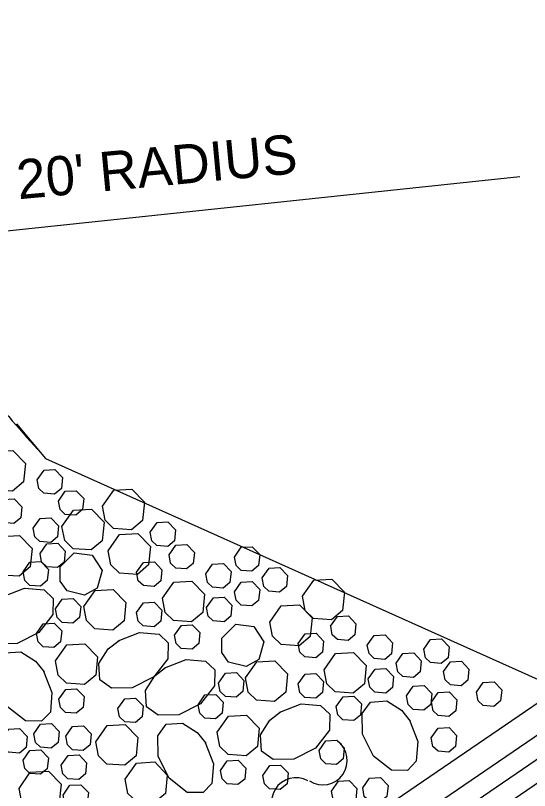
# Model space of a CAD drawing. Extents: x 6709491 to 6710959, y 1869789 to 1870763.
# Drawn here: x 6709842.4 to 6709921, y 1870319.2 to 1870437.5 of the extents above; entities that cross this region are included whole.
import ezdxf

# ---------------------------------------------------------------- set-up
doc = ezdxf.new("R2010")
doc.units = 0
for name, color, linetype in [('56 Stg 3 Anno', 7, 'Continuous'), ('57 Undefined', 7, 'Continuous'), ('60 Nongeo Data', 7, 'Continuous')]:
    doc.layers.add(name, color=color, linetype=linetype)

msp = doc.modelspace()

# ---------------------------------------------------------------- linework, layer by layer
at = {"layer": '56 Stg 3 Anno'}
msp.add_line((6709828.3, 1870403.28), (6709919.48, 1870412.91), dxfattribs=at)
at = {"layer": '60 Nongeo Data'}
for p, q in [((6709846.99, 1870369.89), (6709929.61, 1870332.83)), ((6709845.05, 1870279.98), (6709922.46, 1870332.74)), ((6709851.95, 1870279.8), (6709924.47, 1870329.23)), ((6709855.14, 1870278.31), (6709927.7, 1870327.77)), ((6709858.32, 1870276.81), (6709928.82, 1870324.87))]:
    msp.add_line(p, q, dxfattribs=at)
for points in [[(6709842.58, 1870375.18), (6709846.99, 1870369.89)], [(6709837.48, 1870368.48), (6709839.22, 1870370.95), (6709841.99, 1870371.11), (6709843.92, 1870369.11), (6709843.65, 1870366.3), (6709841.93, 1870364.88), (6709839.19, 1870365.08), (6709837.9, 1870366.33), (6709837.48, 1870368.48)], [(6709845.72, 1870366.6), (6709846.76, 1870368.09), (6709848.43, 1870368.18), (6709849.59, 1870366.98), (6709849.42, 1870365.3), (6709848.39, 1870364.44), (6709846.74, 1870364.56), (6709845.97, 1870365.31), (6709845.72, 1870366.6)], [(6709848.97, 1870363.37), (6709850.02, 1870364.86), (6709851.68, 1870364.95), (6709852.84, 1870363.75), (6709852.67, 1870362.07), (6709851.64, 1870361.21), (6709850, 1870361.33), (6709849.22, 1870362.08), (6709848.97, 1870363.37)], [(6709855.68, 1870362.58), (6709857.41, 1870365.05), (6709860.19, 1870365.21), (6709862.12, 1870363.21), (6709861.84, 1870360.4), (6709860.13, 1870358.98), (6709857.38, 1870359.18), (6709856.09, 1870360.43), (6709855.68, 1870362.58)], [(6709839.49, 1870362.12), (6709840.54, 1870363.61), (6709842.2, 1870363.7), (6709843.36, 1870362.5), (6709843.2, 1870360.82), (6709842.17, 1870359.96), (6709840.52, 1870360.08), (6709839.75, 1870360.83), (6709839.5, 1870362.12)], [(6709849.51, 1870359.5), (6709851.25, 1870361.97), (6709854.02, 1870362.13), (6709855.95, 1870360.13), (6709855.67, 1870357.32), (6709853.96, 1870355.9), (6709851.22, 1870356.1), (6709849.93, 1870357.35), (6709849.51, 1870359.5)], [(6709845.1, 1870359.22), (6709846.15, 1870360.7), (6709847.81, 1870360.8), (6709848.97, 1870359.6), (6709848.8, 1870357.92), (6709847.78, 1870357.06), (6709846.13, 1870357.18), (6709845.36, 1870357.93), (6709845.11, 1870359.22)], [(6709863, 1870358.61), (6709864.04, 1870360.09), (6709865.71, 1870360.19), (6709866.86, 1870358.99), (6709866.7, 1870357.3), (6709865.67, 1870356.45), (6709864.02, 1870356.57), (6709863.25, 1870357.32), (6709863, 1870358.61)], [(6709867.9, 1870359.51), (6709867.9, 1870359.51)], [(6709838.49, 1870355.48), (6709840.22, 1870357.96), (6709843, 1870358.11), (6709844.93, 1870356.11), (6709844.65, 1870353.31), (6709842.94, 1870351.88), (6709840.2, 1870352.08), (6709838.9, 1870353.33), (6709838.49, 1870355.48)], [(6709856.58, 1870355.78), (6709858.32, 1870358.26), (6709861.1, 1870358.42), (6709863.03, 1870356.41), (6709862.75, 1870353.61), (6709861.03, 1870352.18), (6709858.29, 1870352.38), (6709857, 1870353.63), (6709856.58, 1870355.78)], [(6709846.15, 1870355.37), (6709847.19, 1870356.85), (6709848.86, 1870356.95), (6709850.02, 1870355.74), (6709849.85, 1870354.06), (6709848.82, 1870353.21), (6709847.17, 1870353.33), (6709846.4, 1870354.08), (6709846.15, 1870355.36)], [(6709865.87, 1870355.16), (6709866.91, 1870356.64), (6709868.58, 1870356.74), (6709869.74, 1870355.54), (6709869.57, 1870353.85), (6709868.54, 1870353), (6709866.9, 1870353.12), (6709866.12, 1870353.87), (6709865.87, 1870355.16)], [(6709875.86, 1870354.82), (6709876.91, 1870356.31), (6709878.57, 1870356.4), (6709879.73, 1870355.2), (6709879.56, 1870353.52), (6709878.53, 1870352.66), (6709876.89, 1870352.78), (6709876.11, 1870353.53), (6709875.86, 1870354.82)], [(6709849.21, 1870353.33), (6709851.37, 1870355.45), (6709854.13, 1870355.1), (6709855.67, 1870352.78), (6709854.88, 1870350.07), (6709852.94, 1870348.98), (6709850.28, 1870349.67), (6709849.23, 1870351.14), (6709849.21, 1870353.33)], [(6709843.56, 1870352.54), (6709844.6, 1870354.02), (6709846.27, 1870354.12), (6709847.43, 1870352.92), (6709847.26, 1870351.24), (6709846.23, 1870350.38), (6709844.58, 1870350.5), (6709843.81, 1870351.25), (6709843.56, 1870352.54)], [(6709860.92, 1870352.5), (6709861.97, 1870353.99), (6709863.63, 1870354.08), (6709864.79, 1870352.88), (6709864.62, 1870351.2), (6709863.59, 1870350.34), (6709861.95, 1870350.46), (6709861.17, 1870351.21), (6709860.92, 1870352.5)], [(6709871.48, 1870352.25), (6709872.52, 1870353.74), (6709874.19, 1870353.83), (6709875.35, 1870352.63), (6709875.18, 1870350.95), (6709874.15, 1870350.09), (6709872.51, 1870350.21), (6709871.73, 1870350.96), (6709871.48, 1870352.25)], [(6709880.11, 1870351.63), (6709881.16, 1870353.12), (6709882.82, 1870353.21), (6709883.98, 1870352.01), (6709883.81, 1870350.33), (6709882.78, 1870349.47), (6709881.14, 1870349.59), (6709880.36, 1870350.34), (6709880.11, 1870351.63)], [(6709864.86, 1870348.52), (6709866.6, 1870350.99), (6709869.38, 1870351.15), (6709871.31, 1870349.15), (6709871.03, 1870346.34), (6709869.31, 1870344.92), (6709866.57, 1870345.11), (6709865.28, 1870346.36), (6709864.86, 1870348.52)], [(6709875.86, 1870349.51), (6709876.91, 1870350.99), (6709878.57, 1870351.09), (6709879.73, 1870349.88), (6709879.56, 1870348.2), (6709878.53, 1870347.35), (6709876.89, 1870347.47), (6709876.11, 1870348.22), (6709875.86, 1870349.51)], [(6709886.25, 1870348.84), (6709887.99, 1870351.31), (6709890.76, 1870351.47), (6709892.69, 1870349.47), (6709892.41, 1870346.66), (6709890.7, 1870345.24), (6709887.96, 1870345.43), (6709886.67, 1870346.68), (6709886.25, 1870348.83)], [(6709840.52, 1870348.79), (6709843.77, 1870350.08), (6709846.76, 1870349.82), (6709848.18, 1870348.47), (6709848.13, 1870346.05), (6709845.98, 1870343.29), (6709842.65, 1870341.63), (6709839.51, 1870341.57), (6709837.74, 1870342.83), (6709837.57, 1870345.33), (6709839.01, 1870347.57), (6709840.65, 1870348.88)], [(6709852.83, 1870347.26), (6709854.57, 1870349.73), (6709857.35, 1870349.89), (6709859.28, 1870347.89), (6709859, 1870345.08), (6709857.29, 1870343.66), (6709854.54, 1870343.86), (6709853.25, 1870345.11), (6709852.84, 1870347.26)], [(6709848.5, 1870346.89), (6709849.55, 1870348.37), (6709851.21, 1870348.47), (6709852.37, 1870347.27), (6709852.2, 1870345.59), (6709851.17, 1870344.73), (6709849.53, 1870344.85), (6709848.75, 1870345.6), (6709848.5, 1870346.89)], [(6709871.61, 1870347.11), (6709872.66, 1870348.6), (6709874.32, 1870348.69), (6709875.48, 1870347.49), (6709875.31, 1870345.81), (6709874.28, 1870344.95), (6709872.64, 1870345.07), (6709871.86, 1870345.82), (6709871.61, 1870347.11)], [(6709892.6, 1870348.62), (6709892.6, 1870348.62)], [(6709860.91, 1870346.34), (6709861.96, 1870347.82), (6709863.62, 1870347.92), (6709864.78, 1870346.71), (6709864.61, 1870345.03), (6709863.58, 1870344.18), (6709861.94, 1870344.3), (6709861.16, 1870345.05), (6709860.91, 1870346.34)], [(6709881.29, 1870344.89), (6709883.02, 1870347.36), (6709885.8, 1870347.52), (6709887.73, 1870345.52), (6709887.45, 1870342.71), (6709885.74, 1870341.29), (6709882.99, 1870341.49), (6709881.7, 1870342.74), (6709881.29, 1870344.89)], [(6709890.57, 1870344.26), (6709891.62, 1870345.75), (6709893.28, 1870345.84), (6709894.44, 1870344.64), (6709894.28, 1870342.96), (6709893.25, 1870342.1), (6709891.6, 1870342.22), (6709890.83, 1870342.97), (6709890.58, 1870344.26)], [(6709845.6, 1870343.17), (6709846.64, 1870344.65), (6709848.31, 1870344.75), (6709849.47, 1870343.55), (6709849.3, 1870341.86), (6709848.27, 1870341.01), (6709846.63, 1870341.13), (6709845.85, 1870341.88), (6709845.6, 1870343.17)], [(6709866.72, 1870342.9), (6709867.76, 1870344.39), (6709869.43, 1870344.48), (6709870.59, 1870343.28), (6709870.42, 1870341.6), (6709869.39, 1870340.74), (6709867.75, 1870340.86), (6709866.97, 1870341.61), (6709866.72, 1870342.9)], [(6709873.92, 1870342.43), (6709876.07, 1870344.55), (6709878.83, 1870344.2), (6709880.37, 1870341.88), (6709879.59, 1870339.18), (6709877.64, 1870338.09), (6709874.98, 1870338.78), (6709873.94, 1870340.24), (6709873.92, 1870342.43)], [(6709858.09, 1870342.02), (6709861.35, 1870343.31), (6709864.34, 1870343.05), (6709865.76, 1870341.7), (6709865.71, 1870339.28), (6709863.55, 1870336.52), (6709860.22, 1870334.85), (6709857.08, 1870334.8), (6709855.31, 1870336.05), (6709855.15, 1870338.56), (6709856.58, 1870340.79), (6709858.23, 1870342.1)], [(6709885.63, 1870341.61), (6709886.67, 1870343.09), (6709888.34, 1870343.19), (6709889.49, 1870341.99), (6709889.33, 1870340.3), (6709888.3, 1870339.45), (6709886.65, 1870339.57), (6709885.88, 1870340.32), (6709885.63, 1870341.61)], [(6709896.18, 1870341.36), (6709897.23, 1870342.84), (6709898.89, 1870342.94), (6709900.05, 1870341.74), (6709899.88, 1870340.05), (6709898.85, 1870339.2), (6709897.21, 1870339.32), (6709896.44, 1870340.07), (6709896.18, 1870341.36)], [(6709904.82, 1870340.74), (6709905.86, 1870342.22), (6709907.53, 1870342.32), (6709908.68, 1870341.11), (6709908.52, 1870339.43), (6709907.49, 1870338.58), (6709905.84, 1870338.7), (6709905.07, 1870339.45), (6709904.82, 1870340.74)], [(6709848.5, 1870338.95), (6709850.24, 1870341.43), (6709853.02, 1870341.58), (6709854.95, 1870339.58), (6709854.67, 1870336.78), (6709852.96, 1870335.35), (6709850.21, 1870335.55), (6709848.93, 1870336.8), (6709848.51, 1870338.95)], [(6709846.69, 1870337.41), (6709847.98, 1870334.15), (6709847.73, 1870331.16), (6709846.37, 1870329.74), (6709843.95, 1870329.79), (6709841.19, 1870331.94), (6709839.53, 1870335.28), (6709839.47, 1870338.42), (6709840.73, 1870340.19), (6709843.23, 1870340.35), (6709845.47, 1870338.92), (6709846.78, 1870337.28)], [(6709889.57, 1870337.62), (6709891.3, 1870340.09), (6709894.08, 1870340.25), (6709896.01, 1870338.25), (6709895.73, 1870335.45), (6709894.02, 1870334.02), (6709891.28, 1870334.22), (6709889.98, 1870335.47), (6709889.57, 1870337.62)], [(6709900.57, 1870338.61), (6709901.61, 1870340.1), (6709903.28, 1870340.19), (6709904.43, 1870338.99), (6709904.27, 1870337.31), (6709903.24, 1870336.45), (6709901.59, 1870336.57), (6709900.82, 1870337.32), (6709900.57, 1870338.61)], [(6709865.22, 1870337.9), (6709868.47, 1870339.19), (6709871.46, 1870338.93), (6709872.88, 1870337.58), (6709872.84, 1870335.15), (6709870.68, 1870332.4), (6709867.35, 1870330.73), (6709864.21, 1870330.68), (6709862.44, 1870331.93), (6709862.28, 1870334.43), (6709863.71, 1870336.67), (6709865.35, 1870337.98)], [(6709877.54, 1870336.36), (6709879.28, 1870338.84), (6709882.05, 1870339), (6709883.98, 1870336.99), (6709883.71, 1870334.19), (6709881.99, 1870332.76), (6709879.25, 1870332.96), (6709877.96, 1870334.21), (6709877.54, 1870336.36)], [(6709907.84, 1870337.34), (6709908.89, 1870338.83), (6709910.55, 1870338.92), (6709911.71, 1870337.72), (6709911.54, 1870336.04), (6709910.51, 1870335.18), (6709908.87, 1870335.3), (6709908.09, 1870336.05), (6709907.84, 1870337.34)], [(6709896.32, 1870336.22), (6709897.36, 1870337.7), (6709899.03, 1870337.8), (6709900.18, 1870336.6), (6709900.02, 1870334.92), (6709898.99, 1870334.06), (6709897.34, 1870334.18), (6709896.57, 1870334.93), (6709896.32, 1870336.22)], [(6709873.45, 1870335.59), (6709874.49, 1870337.07), (6709876.16, 1870337.17), (6709877.32, 1870335.97), (6709877.15, 1870334.28), (6709876.12, 1870333.43), (6709874.48, 1870333.55), (6709873.7, 1870334.3), (6709873.45, 1870335.59)], [(6709885.62, 1870335.44), (6709886.66, 1870336.92), (6709888.33, 1870337.02), (6709889.49, 1870335.82), (6709889.32, 1870334.14), (6709888.29, 1870333.28), (6709886.64, 1870333.4), (6709885.87, 1870334.15), (6709885.62, 1870335.44)], [(6709902.17, 1870333.61), (6709903.21, 1870335.09), (6709904.88, 1870335.19), (6709906.03, 1870333.99), (6709905.87, 1870332.31), (6709904.84, 1870331.45), (6709903.19, 1870331.57), (6709902.42, 1870332.32), (6709902.17, 1870333.61)], [(6709912.85, 1870334.18), (6709913.9, 1870335.66), (6709915.56, 1870335.76), (6709916.72, 1870334.55), (6709916.56, 1870332.87), (6709915.53, 1870332.02), (6709913.88, 1870332.14), (6709913.11, 1870332.89), (6709912.86, 1870334.18)], [(6709849.03, 1870333.13), (6709850.08, 1870334.61), (6709851.74, 1870334.71), (6709852.9, 1870333.51), (6709852.73, 1870331.83), (6709851.7, 1870330.97), (6709850.06, 1870331.09), (6709849.28, 1870331.84), (6709849.03, 1870333.13)], [(6709870.3, 1870332.27), (6709871.35, 1870333.76), (6709873.01, 1870333.85), (6709874.17, 1870332.65), (6709874, 1870330.97), (6709872.98, 1870330.11), (6709871.33, 1870330.23), (6709870.56, 1870330.98), (6709870.3, 1870332.27)], [(6709905.99, 1870332.66), (6709907.03, 1870334.14), (6709908.7, 1870334.24), (6709909.86, 1870333.03), (6709909.69, 1870331.35), (6709908.66, 1870330.5), (6709907.01, 1870330.61), (6709906.24, 1870331.36), (6709905.99, 1870332.65)], [(6709858.06, 1870331.7), (6709859.11, 1870333.19), (6709860.77, 1870333.28), (6709861.93, 1870332.08), (6709861.76, 1870330.4), (6709860.74, 1870329.54), (6709859.09, 1870329.66), (6709858.32, 1870330.41), (6709858.07, 1870331.7)], [(6709891.42, 1870332.01), (6709892.47, 1870333.49), (6709894.13, 1870333.59), (6709895.29, 1870332.39), (6709895.13, 1870330.7), (6709894.1, 1870329.85), (6709892.45, 1870329.97), (6709891.68, 1870330.72), (6709891.43, 1870332.01)], [(6709902.63, 1870329.91), (6709903.92, 1870326.65), (6709903.66, 1870323.66), (6709902.31, 1870322.24), (6709899.88, 1870322.29), (6709897.13, 1870324.44), (6709895.46, 1870327.78), (6709895.4, 1870330.92), (6709896.66, 1870332.68), (6709899.16, 1870332.85), (6709901.4, 1870331.42), (6709902.71, 1870329.78)], [(6709882.8, 1870331.13), (6709886.05, 1870332.42), (6709889.04, 1870332.16), (6709890.46, 1870330.81), (6709890.41, 1870328.38), (6709888.26, 1870325.63), (6709884.93, 1870323.96), (6709881.79, 1870323.9), (6709880.02, 1870325.16), (6709879.85, 1870327.66), (6709881.29, 1870329.9), (6709882.93, 1870331.21)], [(6709873.21, 1870328.06), (6709874.95, 1870330.53), (6709877.72, 1870330.69), (6709879.66, 1870328.69), (6709879.38, 1870325.88), (6709877.66, 1870324.46), (6709874.92, 1870324.65), (6709873.63, 1870325.91), (6709873.21, 1870328.06)], [(6709845.21, 1870327.82), (6709846.25, 1870329.3), (6709847.92, 1870329.4), (6709849.08, 1870328.2), (6709848.91, 1870326.51), (6709847.88, 1870325.66), (6709846.23, 1870325.78), (6709845.46, 1870326.53), (6709845.21, 1870327.82)], [(6709854.67, 1870326.62), (6709856.41, 1870329.09), (6709859.19, 1870329.25), (6709861.12, 1870327.25), (6709860.84, 1870324.45), (6709859.12, 1870323.02), (6709856.38, 1870323.22), (6709855.09, 1870324.47), (6709854.67, 1870326.62)], [(6709871.4, 1870326.51), (6709872.69, 1870323.26), (6709872.43, 1870320.27), (6709871.08, 1870318.85), (6709868.65, 1870318.89), (6709865.9, 1870321.05), (6709864.23, 1870324.38), (6709864.18, 1870327.52), (6709865.43, 1870329.29), (6709867.93, 1870329.46), (6709870.17, 1870328.02), (6709871.48, 1870326.38)], [(6709840.32, 1870327.06), (6709841.36, 1870328.54), (6709843.03, 1870328.64), (6709844.19, 1870327.43), (6709844.02, 1870325.75), (6709842.99, 1870324.9), (6709841.35, 1870325.02), (6709840.57, 1870325.77), (6709840.32, 1870327.05)], [(6709850.1, 1870327.45), (6709851.14, 1870328.93), (6709852.81, 1870329.03), (6709853.96, 1870327.83), (6709853.8, 1870326.15), (6709852.77, 1870325.29), (6709851.12, 1870325.41), (6709850.35, 1870326.16), (6709850.1, 1870327.45)], [(6709905.96, 1870327.21), (6709907.01, 1870328.69), (6709908.67, 1870328.79), (6709909.83, 1870327.59), (6709909.66, 1870325.9), (6709908.63, 1870325.05), (6709906.99, 1870325.17), (6709906.21, 1870325.92), (6709905.96, 1870327.21)], [(6709888.8, 1870325.3), (6709889.84, 1870326.78), (6709891.51, 1870326.88), (6709892.66, 1870325.68), (6709892.5, 1870324), (6709891.47, 1870323.14), (6709889.82, 1870323.26), (6709889.05, 1870324.01), (6709888.8, 1870325.3)], [(6709843.56, 1870323.82), (6709844.6, 1870325.3), (6709846.27, 1870325.39), (6709847.43, 1870324.19), (6709847.26, 1870322.51), (6709846.23, 1870321.65), (6709844.58, 1870321.77), (6709843.81, 1870322.52), (6709843.56, 1870323.81)], [(6709849.4, 1870323.02), (6709850.44, 1870324.51), (6709852.11, 1870324.6), (6709853.27, 1870323.4), (6709853.1, 1870321.72), (6709852.07, 1870320.86), (6709850.42, 1870320.98), (6709849.65, 1870321.73), (6709849.4, 1870323.02)], [(6709859.17, 1870320.89), (6709860.91, 1870323.37), (6709863.68, 1870323.53), (6709865.61, 1870321.52), (6709865.33, 1870318.72), (6709863.62, 1870317.29), (6709860.88, 1870317.49), (6709859.59, 1870318.74), (6709859.17, 1870320.89)], [(6709873.74, 1870322.24), (6709874.78, 1870323.72), (6709876.45, 1870323.82), (6709877.6, 1870322.61), (6709877.44, 1870320.93), (6709876.41, 1870320.08), (6709874.76, 1870320.19), (6709873.99, 1870320.94), (6709873.74, 1870322.23)], [(6709842.94, 1870319.5), (6709844.67, 1870321.97), (6709847.45, 1870322.13), (6709849.38, 1870320.13), (6709849.1, 1870317.33), (6709847.39, 1870315.9), (6709844.64, 1870316.1), (6709843.35, 1870317.35), (6709842.94, 1870319.5)], [(6709880.21, 1870321.48), (6709881.26, 1870322.97), (6709882.92, 1870323.06), (6709884.08, 1870321.86), (6709883.91, 1870320.18), (6709882.88, 1870319.32), (6709881.24, 1870319.44), (6709880.47, 1870320.19), (6709880.21, 1870321.48)], [(6709895.47, 1870319.58), (6709896.52, 1870321.06), (6709898.18, 1870321.15), (6709899.34, 1870319.95), (6709899.17, 1870318.27), (6709898.14, 1870317.42), (6709896.5, 1870317.53), (6709895.72, 1870318.28), (6709895.47, 1870319.58)], [(6709849.68, 1870318.48), (6709850.73, 1870319.97), (6709852.39, 1870320.06), (6709853.55, 1870318.86), (6709853.38, 1870317.18), (6709852.35, 1870316.32), (6709850.71, 1870316.44), (6709849.94, 1870317.19), (6709849.68, 1870318.48)], [(6709890.7, 1870319.1), (6709891.75, 1870320.58), (6709893.41, 1870320.68), (6709894.57, 1870319.48), (6709894.4, 1870317.79), (6709893.37, 1870316.94), (6709891.73, 1870317.06), (6709890.96, 1870317.81), (6709890.7, 1870319.1)]]:
    msp.add_lwpolyline(points, dxfattribs=at)
for centre, start, end in [((6709889.39, 1870323.75), 236.7831, 53.1436), ((6709885.26, 1870317.41), 60.4986, 236.8591)]:
    msp.add_arc(centre, 3.72, start, end, dxfattribs=at)
msp.add_spline([(6709839.39, 1870450.83), (6709831.86, 1870436.12), (6709837.31, 1870381.57), (6709845.79, 1870371.27)], degree=3, dxfattribs=at)

# ---------------------------------------------------------------- texts
at = {"layer": '57 Undefined'}
msp.add_text("20' RADIUS", height=6, rotation=5.3581, dxfattribs=at).set_placement((6709842.86, 1870409.44))

doc.saveas('drawing.dxf')
